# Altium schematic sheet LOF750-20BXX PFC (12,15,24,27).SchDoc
size A4; Revision: A; SheetNumber: 1; SheetTotal: 1
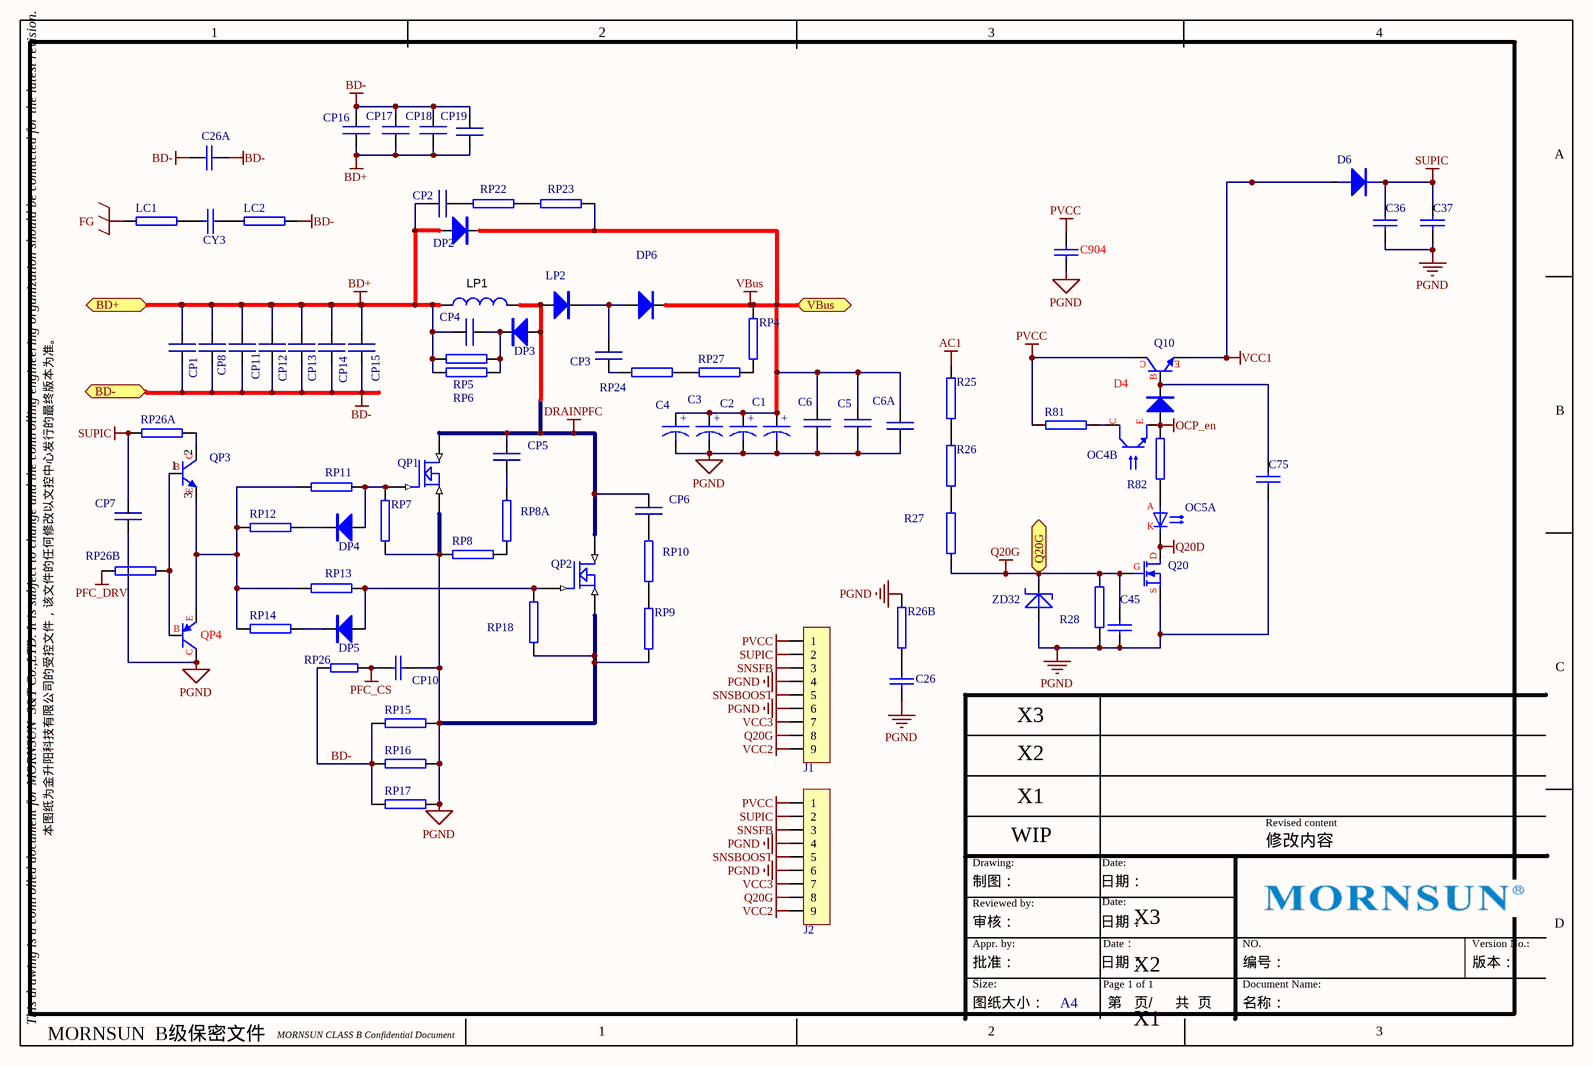
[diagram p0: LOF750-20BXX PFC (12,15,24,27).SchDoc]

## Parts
C1  220u/400V/Φ22*36  [EC-7.5-16.0X25.0-V]  (value not drawn)
C2  220u/400V/Φ22*36  [EC-7.5-16.0X25.0-V]  (value not drawn)
C3  220u/400V/Φ22*36  [EC-7.5-16.0X25.0-V]  (value not drawn)
C4  220u/400V/Φ22*36  [EC-7.5-16.0X25.0-V]  (value not drawn)
C5  NC  [S1206-C&S1210-C]  (value not drawn)
C6  NC  [S1206-C&S1210-C]  (value not drawn)
C6A  NC  [S1206-C&S1210-C]  (value not drawn)
C26  0603  [SC-0603]  (value not drawn)
C26A  0603  [SC-0603]  (value not drawn)
C36  1206  [SC-0805]  (value not drawn)
C37  1206  [SC-0805]  (value not drawn)
C45  0603  [SC-0603]  (value not drawn)
C75  1206  [SC-0805]  (value not drawn)
C904  0805  [SC-0805]  (value not drawn)
CP1  225/450V/15*18*11;P=15  [CAP-15-18.0X10.0-X]  (value not drawn)
CP2  1206  [SC-1206]  (value not drawn)
CP3  1206  [SC-1206]  (value not drawn)
CP4  1206  [SC-1206]  (value not drawn)
CP5  1206  [SC-1206]  (value not drawn)
CP6  1206  [SC-1206]  (value not drawn)
CP7  1206  [SC-1206]  (value not drawn)
CP8  1206  [S1206-C&S1210-C]  (value not drawn)
CP10  473/50V/0603  [SC-0805]  (value not drawn)
CP11  1206  [S1206-C&S1210-C]  (value not drawn)
CP12  1206  [S1206-C&S1210-C]  (value not drawn)
CP13  1206  [S1206-C&S1210-C]  (value not drawn)
CP14  1206  [S1206-C&S1210-C]  (value not drawn)
CP15  1206  [S1206-C&S1210-C]  (value not drawn)
CP16  1206  [SC-1206]  (value not drawn)
CP17  1206  [SC-1206]  (value not drawn)
CP18  1206  [SC-1206]  (value not drawn)
CP19  1206  [SC-1206]  (value not drawn)
CY3  y1 2n2  [SC-T7-Y1]  (value not drawn)
D4  SOD-323  [SOD-323]  (value not drawn)
D6  SOD323  [SOD-323]  (value not drawn)
DP2  S3J/SMC  [SD-SMC]  (value not drawn)
DP3  SOD123  [SOD-123&SD-1206]  (value not drawn)
DP4  SOD123  [SOD-123&SD-1206]  (value not drawn)
DP5  SOD123  [SOD-123&SD-1206]  (value not drawn)
DP6  TO-220  [SD-DPAK]  (value not drawn)
J1  MHDR1X9  [CON-2.0-9P-S(插主板)]  (value not drawn)
J2  MHDR1X9  [CON-2.0-9P-S(插小板)]  (value not drawn)
LC1  27k/0603  [SL-0805]  (value not drawn)
LC2  27k/0603  [SL-0805]  (value not drawn)
LP1  (no value)  [750W-LP1]
LP2  TO-220  [SD-SMB]  (value not drawn)
OC4  (no value)  [SOPT-101]  (part B of 2)
OC5  OC  [SOPT-101]  (value not drawn)  (part A of 2)
Q10  sot-89  [SOT-89]  (value not drawn)
Q20  SOT23  [SOT-23A]  (value not drawn)
QP1  60S2088/TO-247  [TO247-3]  (value not drawn)
QP2  TO-247  [TO247-3]  (value not drawn)
QP3  SOT23  [SOT-23A]  (value not drawn)
QP4  SOT23  [SOT-23A]  (value not drawn)
R25  1M/1206  [SR-1206]  (value not drawn)
R26  1M/1206  [SR-1206]  (value not drawn)
R26B  0603  [SR-0603]  (value not drawn)
R27  1M/1206  [SR-1206]  (value not drawn)
R28  270K/0603  [SR-0603]  (value not drawn)
R81  1k/0603  [SR-0603]  (value not drawn)
R82  27k/0603  [SR-0603]  (value not drawn)
RP4  2M/1206  [SR-1206]  (value not drawn)
RP5  1206  [SR-1206]  (value not drawn)
RP6  1206  [SR-1206]  (value not drawn)
RP7  10k/0603  [SR-0603]  (value not drawn)
RP8  2M/1206  [SR-1206]  (value not drawn)
RP8A  2M/1206  [SR-1206]  (value not drawn)
RP9  2M/1206  [SR-1206]  (value not drawn)
RP10  2M/1206  [SR-1206]  (value not drawn)
RP11  1206  [SR-1206]  (value not drawn)
RP12  1206  [SR-1206]  (value not drawn)
RP13  1206  [SR-1206]  (value not drawn)
RP14  1206  [SR-1206]  (value not drawn)
RP15  2512  [SR-2512]  (value not drawn)
RP16  0.05/3WJ  [SR-2512]  (value not drawn)
RP17  0.05/3WJ  [SR-2512]  (value not drawn)
RP18  10k/0603  [SR-0603]  (value not drawn)
RP22  2M/1206  [SR-1206]  (value not drawn)
RP23  2M/1206  [SR-1206]  (value not drawn)
RP24  2M/1206  [SR-1206]  (value not drawn)
RP26  12K/0603  [SR-0805]  (value not drawn)
RP26A  0805  [SR-0805]  (value not drawn)
RP26B  0805  [SR-0805]  (value not drawn)
RP27  2M/1206  [SR-1206]  (value not drawn)
ZD32  SOD123  [SOD-123&SD-1206]  (value not drawn)

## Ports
BD+ (bidir), BD- (bidir), Q20G (bidir), VBus (bidir)

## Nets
AC1: R25.1
BD+: CP1.1 CP2.1 CP4.1 CP8.1 CP11.1 CP12.1 CP13.1 CP14.1 CP15.1 CP16.2 CP17.2 CP18.2 CP19.2 DP2.1(A) LP1.3 RP5.2 RP6.2 ; port BD+
BD-: C26A.1 C26A.2 CP1.2 CP8.2 CP11.2 CP12.2 CP13.2 CP14.2 CP15.2 CP16.1 CP17.1 CP18.1 CP19.1 LC2.1 RP15.2 RP16.2 RP17.2 RP26.1 ; port BD-
DRAINPFC: CP5.1 CP6.1 DP3.1(A) LP1.5 LP2.1(A) QP1.2(D) QP2.2(D)
FG: LC1.2
OCP_en: D4.1(A) OC4.3(E) R82.2
PFC_CS: CP10.1 RP26.2
PFC_DRV: RP26B.2
PGND: C1.2 C2.2 C3.2 C4.2 C5.1 C6.2 C6A.2 C26.2 C36.1 C37.1 C45.1 C75.1 C904.1 CP7.2 CP10.2 J1.4 J1.6 J2.4 J2.6 Q20.3(S) QP1.3(S) QP2.3(S) QP4.2(C) R26B.1 R28.2 RP7.2 RP8.2 RP9.2 RP15.1 RP16.1 RP17.1 RP18.2 ZD32.1(A)
PVCC: C904.2 J1.1 J2.1 Q10.2(C) R81.1
Q20D: OC5.2(K) Q20.2(D)
Q20G: C45.2 J1.8 J2.8 Q20.1(G) R27.2 R28.1 ZD32.2(K) ; port Q20G
SNSBOOST: J1.5 J2.5
SNSFB: J1.3 J2.3
SUPIC: C36.2 C37.2 CP7.1 D6.2(K) J1.2 J2.2 RP26A.2
VBus: C1.1 C2.1 C3.1 C4.1 C5.2 C6.1 C6A.1 DP2.2(K) DP6.2(K) RP4.1 RP23.1 ; port VBus
VCC1: D6.1(A) Q10.3(E)
VCC2: J1.9 J2.9
VCC3: J1.7 J2.7
NetC26_1: C26.1 R26B.2
NetC75_2: C75.2 D4.2(K) Q10.1(B)
NetCP2_2: CP2.2 RP22.2
NetCP3_1: CP3.1 DP6.3(A) LP2.2(K)
NetCP3_2: CP3.2 RP24.2
NetCP4_2: CP4.2 DP3.2(K) RP5.1 RP6.1
NetCP5_2: CP5.2 RP8A.2
NetCP6_2: CP6.2 RP10.2
NetCY3_1: CY3.1 LC1.1
NetCY3_2: CY3.2 LC2.2
NetDP4_1: DP4.1(A) QP1.1(G) RP7.1 RP11.2
NetDP4_2: DP4.2(K) RP12.1
NetDP5_1: DP5.1(A) QP2.1(G) RP13.2 RP18.1
NetDP5_2: DP5.2(K) RP14.1
NetOC4_4: OC4.4(C) R81.2
NetOC5_1: OC5.1(A) R82.1
NetQP3_1: QP3.1(B) QP4.1(B) RP26B.1
NetQP3_2: QP3.2(C) RP26A.1
NetQP3_3: QP3.3(E) QP4.3(E) RP11.1 RP12.2 RP13.1 RP14.2
NetR25_2: R25.2 R26.1
NetR26_2: R26.2 R27.1
NetRP4_2: RP4.2 RP27.1
NetRP8_1: RP8.1 RP8A.1
NetRP9_1: RP9.1 RP10.1
NetRP22_1: RP22.1 RP23.2
NetRP24_1: RP24.1 RP27.2

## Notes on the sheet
- 1
- 2
- 3
- 4
- A
- B
- X3
- C
- X2
- 本图纸为金升阳科技有限公司的受控文件，该文件的任何修改以文控中心发行的最终版本为准。
- Drawing:
- WIP
- X1
- Date:
- 修改内容
- Revised content
- Reviewed by:
- 审核：
- 制图：
- 日期：
- D
- Appr. by:
- Size:
- 批准：
- Page 1 of 1
- Date：
- Document Name:
- NO.
- 编号：
- Version No.:
- 版本：
- This drawing is a controlled document for MORNSUN  S&T Co.,LTD. It is subject to change and the controlling engineering organization should be contacted for the latest revision.
- MORNSUN  B级保密文件
- MORNSUN CLASS B Confidential Document
- 图纸大小：
- A4
- 第   页/
- 共  页
- 名称：

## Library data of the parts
C1-C4 = CAPACITOR POL: Capacitor; Mfr: Samxon; MPN: ERD107M2WL35RRS0P
C5 C6 C6A CP2-CP8 CP11-CP19 = CAP-1
C26 C26A C36 C37 C45 C75 C904 = CAP: 103K/50V/0603/X7R; PN: 30010146
CP1 = CAP-1: Mfr: Wanming; MPN: MPE450V225K15S5
CP10 = Cap: Capacitor
CY3 = CAP: MPN: YU1AH222M090BAMD0H; PN: 30040010; APN: ??
D4 DP2-DP5 = DI-1: Mfr: Yangjie; MPN: GS3JB
D6 = DIODE: MPN: SK110; PN: 31000046
DP6 LP2 = DI-1: 600V/10A/TO-220AC; Mfr: Yangjie; MPN: GS3JB
J1 J2 = Pin9
LC1 LC2 R25-R28 R81 R82 = RES1: 2.2MΩ 1/8W ±1% 0805
LP1 = 7840-09-0014: PN: 52104014; APN: ??
OC4 = OC
Q10 QP3 = NPN: NPN Transistor
Q20 = MOSFET N
QP1 QP2 = MOSFET N: Mfr: AOS; MPN: AOT190A60L
QP4 = PNP: PNP Transistor
R26B RP11-RP14 RP26A RP26B = RES1: PN: 35000056
RP4-RP6 RP8 RP8A RP9 RP10 RP15-RP17 RP22-RP24 RP27 = RES1: 2.2MΩ 1/8W ±1% 0805; PN: 35002037
RP7 RP18 = RES1: 20KΩ 1/10W ±1% 0603; PN: 35000029
RP26 = R
ZD32 = Diode 稳压: Zener Diode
